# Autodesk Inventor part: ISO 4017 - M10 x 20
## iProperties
IsCustomPart: 0
Created: 2009-02
Part Number: ISO 4017 - M10 x 20
Material: Stainless Steel, 440C
Description: Hexagon head screws
Document SubType Name: Modeling
Standard: ISO 4017
Designer: 904Chiaki
Standard Revision: Third edition 1999-08-15
Standards Organization: ISO
Language: en-US
Size Designation: M10 x 20
Categories: <MemberInstance><Categories><Category DisplayName="Fasteners" InternalName="e4da775c-781d-43d5-af7c-5136215cf5a6" Mnemonic="FSTN"><Category DisplayName="Bolts"
Density: 7.75 g/cm^3
Author: 904Chiaki
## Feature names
1. Body [Revolution]
2. Head [Extrusion]
3. Chamfer1 [Revolution]
4. Chamfer2
